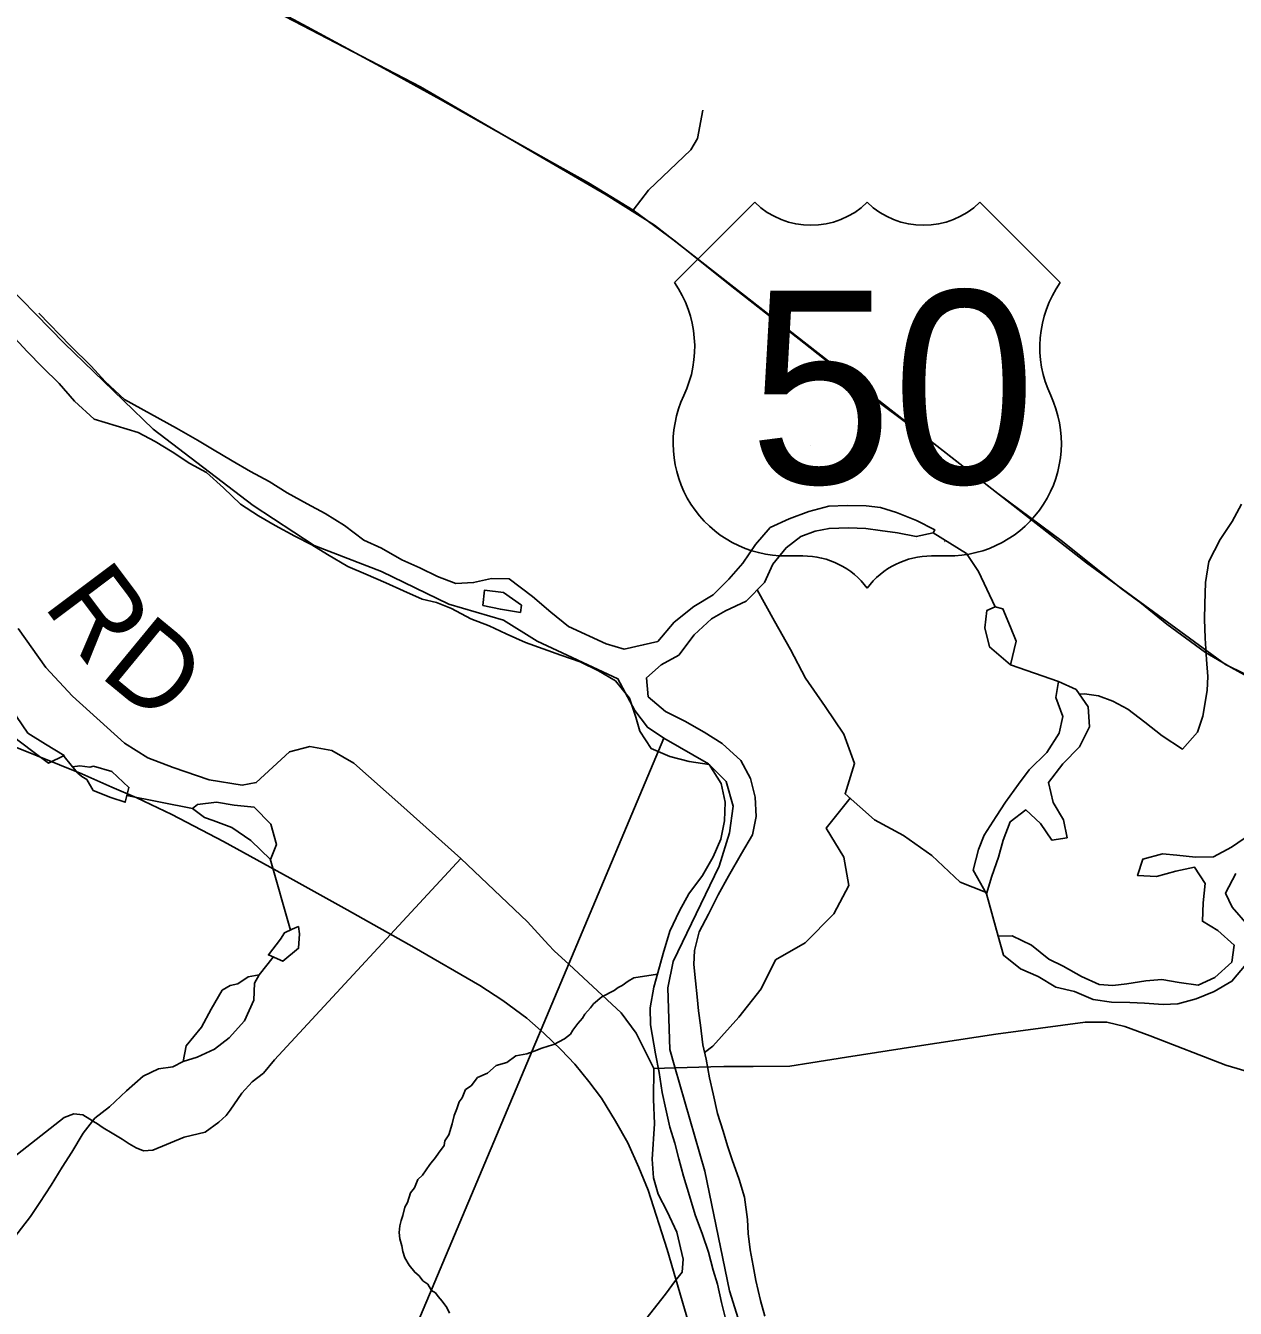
# Model space of a CAD drawing. Extents: x 0 to 34, y 0 to 22.
# Drawn here: x 3.416 to 4.243, y 19.852 to 20.729 of the extents above; entities that cross this region are included whole.
import ezdxf

# ---------------------------------------------------------------- set-up
doc = ezdxf.new("R2010")
doc.units = 0
for name, color, linetype in [('GM_X_Corporation', 7, 'Continuous'), ('GM_X_County_Road', 7, 'Continuous'), ('GM_X_Major_River', 7, 'Continuous'), ('GM_X_Minor_Lake', 7, 'Continuous'), ('GM_X_Minor_River', 7, 'Continuous'), ('GM_X_Rail_Line', 7, 'Continuous'), ('GM_X_Township_Road', 7, 'Continuous'), ('GM_X_Township_Road_Text', 7, 'Continuous'), ('GM_X_US_Location', 7, 'Continuous'), ('GM_X_US_Route', 7, 'Continuous'), ('GM_X_US_Shield', 7, 'Continuous')]:
    doc.layers.add(name, color=color, linetype=linetype)

msp = doc.modelspace()

# ---------------------------------------------------------------- linework, layer by layer
at = {"layer": 'GM_X_Corporation'}
for points in [[(2.97186, 18.15329), (3.78717, 20.08795), (3.85216, 20.24216), (3.84089, 20.24968), (3.83227, 20.26117), (3.82078, 20.28273), (3.76546, 20.3086), (3.74247, 20.32296), (3.70512, 20.33374), (3.65915, 20.35602), (3.61316, 20.37398), (3.5715, 20.40129), (3.50317, 20.45336), (3.44218, 20.5121), (3.34506, 20.61151), (3.32473, 20.67025), (3.32248, 20.70188), (3.35184, 20.80129)], [(3.34506, 20.61151), (3.44218, 20.5121), (3.50317, 20.45336), (3.5715, 20.40129), (3.61316, 20.37398), (3.65915, 20.35602), (3.70512, 20.33374), (3.74247, 20.32296), (3.76546, 20.3086), (3.82078, 20.28273), (3.83227, 20.26117), (3.84089, 20.24968), (3.85216, 20.24216), (3.88265, 20.22457), (3.8947, 20.21252), (3.89951, 20.19566), (3.89711, 20.17758), (3.88987, 20.1547), (3.85856, 20.08964), (3.85494, 20.07157), (3.85615, 20.0294), (3.85963, 20.01736), (3.88023, 19.94628), (3.89709, 19.86435), (3.91876, 19.79448)], [(3.91876, 19.79448), (3.89709, 19.86435), (3.88023, 19.94628), (3.85963, 20.01736), (3.85615, 20.0294), (3.85494, 20.07157), (3.85856, 20.08964), (3.88987, 20.1547), (3.89711, 20.17758), (3.89951, 20.19566), (3.8947, 20.21252), (3.88265, 20.22457), (3.85216, 20.24216), (3.78717, 20.08795), (2.97186, 18.15329)]]:
    msp.add_lwpolyline(points, dxfattribs=at)
at = {"layer": 'GM_X_County_Road'}
for points in [[(3.95265, 20.02035), (3.97685, 20.02411), (4.02527, 20.03179), (4.07902, 20.0398), (4.14002, 20.04807), (4.15481, 20.04815), (4.16716, 20.04514), (4.18452, 20.0388), (4.23628, 20.01876), (4.25397, 20.01343), (4.26232, 20.01251), (4.26966, 20.01275), (4.28062, 20.01725), (4.29626, 20.0276), (4.39506, 20.1048), (4.47516, 20.16515), (4.49823, 20.17943)], [(3.80963, 19.80691), (3.85335, 19.86208), (3.86004, 19.8714), (3.86456, 19.87721), (3.8653, 19.88611), (3.8611, 19.90464), (3.85443, 19.91872), (3.84831, 19.9305), (3.84504, 19.94169), (3.84406, 19.95454), (3.84578, 19.9785), (3.84504, 19.99555), (3.8453, 20.01643)], [(3.8453, 20.01643), (3.85986, 20.01684), (3.88427, 20.01752)], [(3.88427, 20.01752), (3.89305, 20.01776), (3.91308, 20.01776), (3.93812, 20.0181), (3.95265, 20.02035)]]:
    msp.add_lwpolyline(points, dxfattribs=at)
at = {"layer": 'GM_X_Major_River'}
for p, q in [((3.75409, 20.3282), (3.75494, 20.33313)), ((4.08895, 20.29223), (4.09301, 20.30851))]:
    msp.add_line(p, q, dxfattribs=at)
for points in [[(3.42501, 20.5327), (3.44657, 20.5103), (3.46071, 20.49639), (3.47038, 20.48597), (3.48341, 20.47359), (3.51909, 20.45413)], [(3.40581, 20.51854), (3.41696, 20.50657), (3.42737, 20.49576), (3.43891, 20.48455), (3.44931, 20.47259), (3.46272, 20.46021), (3.49283, 20.45115)], [(3.49283, 20.45115), (3.5045, 20.44487), (3.51617, 20.43783), (3.5282, 20.43003), (3.53949, 20.42376), (3.5511, 20.4133), (3.56269, 20.40209), (3.5751, 20.39428), (3.58639, 20.38763), (3.59995, 20.38018), (3.61163, 20.37428), (3.62216, 20.36765), (3.63608, 20.35943), (3.64853, 20.35428), (3.66211, 20.34835), (3.67418, 20.34283), (3.687, 20.33729), (3.69684, 20.33485), (3.70703, 20.33088), (3.72022, 20.32382), (3.73267, 20.31905), (3.74436, 20.31353), (3.75756, 20.30761), (3.78173, 20.29885), (3.79496, 20.29445), (3.80739, 20.28816), (3.81906, 20.2815), (3.82874, 20.26955), (3.83309, 20.25656), (3.8356, 20.24701), (3.84338, 20.2351), (3.85621, 20.22956), (3.86945, 20.2263), (3.88309, 20.22417), (3.89124, 20.21111), (3.89407, 20.19852), (3.89348, 20.1856), (3.891, 20.1731), (3.88587, 20.16102), (3.87844, 20.14822), (3.86912, 20.13582), (3.86286, 20.12414), (3.85617, 20.11019), (3.85175, 20.09505), (3.84811, 20.08181), (3.8453, 20.07197), (3.84279, 20.05794), (3.84298, 20.04616), (3.84646, 20.02633), (3.84891, 20.01374), (3.85097, 20.00002), (3.85344, 19.98858), (3.85628, 19.97636), (3.85952, 19.96529), (3.86239, 19.95459), (3.86562, 19.94275), (3.86958, 19.92938), (3.87355, 19.91639), (3.87865, 19.903), (3.88263, 19.89077), (3.88585, 19.87855), (3.88873, 19.869), (3.89157, 19.85641), (3.89442, 19.84457)], [(3.51909, 20.45413), (3.53339, 20.44591), (3.54355, 20.43966), (3.55709, 20.43183), (3.56951, 20.4244), (3.58232, 20.41773), (3.59473, 20.40992), (3.60828, 20.40247), (3.62071, 20.3958), (3.63387, 20.3876), (3.64701, 20.3775), (3.65908, 20.37197), (3.673, 20.36414), (3.68545, 20.35861), (3.69751, 20.35271), (3.70997, 20.34794), (3.72213, 20.3485), (3.73434, 20.35134), (3.74649, 20.35113), (3.76225, 20.33909), (3.77499, 20.32823), (3.78699, 20.31853), (3.81263, 20.3067), (3.82511, 20.30307), (3.83807, 20.3059), (3.84799, 20.30839), (3.85922, 20.32151), (3.87269, 20.33231), (3.88573, 20.34008), (3.89654, 20.35093), (3.90622, 20.36179), (3.91478, 20.37457), (3.92484, 20.38619), (3.93786, 20.39206), (3.95123, 20.39716), (3.96497, 20.40073), (3.97751, 20.40129), (3.99043, 20.40107), (4.00028, 20.39977), (4.01125, 20.39654), (4.02483, 20.391), (4.03727, 20.38471), (4.03623, 20.38261)], [(4.03623, 20.38261), (4.02465, 20.37998), (4.01178, 20.38247), (4.00003, 20.38418), (3.99017, 20.38549), (3.97841, 20.38606), (3.9651, 20.38552), (3.95558, 20.38378), (3.94564, 20.38015), (3.93564, 20.37233), (3.92672, 20.36107), (3.92082, 20.34862), (3.90845, 20.3359), (3.89429, 20.32929), (3.88471, 20.32375), (3.87275, 20.31292), (3.86227, 20.29903), (3.85039, 20.29239), (3.84037, 20.28343), (3.8413, 20.27049), (3.85329, 20.2604), (3.86648, 20.25372), (3.87965, 20.24628), (3.89206, 20.23847), (3.90479, 20.22685), (3.91143, 20.21458), (3.91464, 20.20198), (3.91519, 20.18867), (3.9127, 20.17616), (3.90528, 20.16336), (3.89629, 20.14792), (3.88925, 20.13511), (3.88257, 20.12192), (3.8763, 20.10985), (3.87305, 20.09698), (3.87252, 20.08749), (3.87386, 20.07644), (3.87482, 20.0654), (3.87581, 20.05588), (3.87716, 20.04597), (3.87885, 20.03264), (3.88097, 20.02272), (3.88342, 20.01013), (3.8859, 19.99907), (3.88873, 19.98571), (3.89271, 19.97348), (3.89558, 19.96355), (3.89885, 19.95399), (3.90357, 19.94061), (3.90717, 19.92838), (3.9092, 19.91314), (3.90981, 19.90362), (3.91115, 19.89258), (3.91325, 19.88152), (3.91499, 19.87161), (3.91818, 19.85787), (3.92105, 19.84717)], [(4.03623, 20.38261), (4.05904, 20.36838), (4.06719, 20.35608), (4.07855, 20.33198)], [(3.75494, 20.33313), (3.74254, 20.3417), (3.72965, 20.34343), (3.72834, 20.33281)], [(3.72834, 20.33281), (3.74046, 20.33032), (3.75409, 20.3282)], [(4.07855, 20.33198), (4.07284, 20.32937), (4.07151, 20.31761), (4.07472, 20.30463), (4.08895, 20.29223)], [(4.09301, 20.30851), (4.08899, 20.31808), (4.08388, 20.33071), (4.07855, 20.33198)], [(4.08895, 20.29223), (4.12182, 20.28104)], [(4.12182, 20.28104), (4.12012, 20.27004), (4.12485, 20.25704), (4.12239, 20.24567), (4.11382, 20.23251), (4.10184, 20.22054), (4.09447, 20.21078), (4.08553, 20.19838), (4.0793, 20.1886), (4.07111, 20.17581), (4.06715, 20.166), (4.06351, 20.15199), (4.07274, 20.13587)], [(4.07274, 20.13587), (4.07636, 20.14797), (4.08074, 20.16083), (4.08397, 20.17256), (4.08873, 20.18503), (4.09951, 20.19321), (4.10961, 20.18392), (4.1174, 20.17238), (4.12769, 20.17411), (4.12522, 20.18632), (4.1182, 20.19822), (4.115, 20.21196), (4.12471, 20.22472), (4.13629, 20.23632), (4.14297, 20.2499), (4.14205, 20.2636), (4.13389, 20.27552), (4.12182, 20.28104)], [(4.25385, 20.17696), (4.24003, 20.16769), (4.22776, 20.16105), (4.2156, 20.16087), (4.20271, 20.16222), (4.19285, 20.16315), (4.17949, 20.15957), (4.17589, 20.14822), (4.1888, 20.14763), (4.20215, 20.15121), (4.21473, 20.15404), (4.22215, 20.14289), (4.2208, 20.12961), (4.22021, 20.11707), (4.23075, 20.11082), (4.24198, 20.10075), (4.24027, 20.08899), (4.22871, 20.07854), (4.21723, 20.0734), (4.20434, 20.07514), (4.19259, 20.07723), (4.18156, 20.07628), (4.16861, 20.07421), (4.1591, 20.07323), (4.14961, 20.07377), (4.13755, 20.07929), (4.12512, 20.08634), (4.11532, 20.09106), (4.10332, 20.10076), (4.09013, 20.10707), (4.08063, 20.10685)], [(4.25132, 20.11428), (4.2405, 20.12662), (4.2361, 20.1362), (4.24316, 20.14977)], [(4.07274, 20.13587), (4.08063, 20.10685)], [(4.08063, 20.10685), (4.08422, 20.09386), (4.09584, 20.08454), (4.10792, 20.0794), (4.11995, 20.07197), (4.13282, 20.0691), (4.14565, 20.06357), (4.15816, 20.06184), (4.17069, 20.06163), (4.18056, 20.06108), (4.19346, 20.06011), (4.20334, 20.06071), (4.21593, 20.06392), (4.22817, 20.06904), (4.24044, 20.07606), (4.25013, 20.08768)]]:
    msp.add_lwpolyline(points, dxfattribs=at)
at = {"layer": 'GM_X_Minor_Lake'}
msp.add_lwpolyline([(4.1361, 20.27229), (4.13966, 20.27243), (4.14915, 20.27113), (4.15898, 20.26754), (4.16916, 20.26204), (4.18079, 20.25309), (4.1928, 20.24375), (4.20672, 20.23477), (4.21682, 20.24637), (4.22043, 20.25734), (4.2234, 20.27477), (4.22395, 20.28426), (4.22301, 20.29607), (4.22212, 20.31053), (4.22159, 20.32346), (4.22177, 20.33372), (4.22241, 20.34854), (4.22456, 20.36294), (4.23243, 20.37801), (4.24064, 20.39041), (4.24693, 20.40209)], dxfattribs=at)
at = {"layer": 'GM_X_Minor_River'}
for points in [[(4.02494, 20.37793), (4.02494, 20.37793)], [(4.04416, 20.37649), (4.04399, 20.37654)], [(3.91597, 20.34363), (3.92778, 20.32209), (3.93879, 20.30271), (3.94904, 20.28332), (3.96233, 20.26394), (3.97524, 20.24493), (3.98246, 20.22479), (3.976, 20.20426), (3.99612, 20.1864), (4.01587, 20.17575), (4.03524, 20.16207), (4.0546, 20.14382), (4.07208, 20.13703)], [(3.36902, 20.31921), (3.37649, 20.31544), (3.38926, 20.30647), (3.39971, 20.2945), (3.40367, 20.28189), (3.40649, 20.26892), (3.40971, 20.25707), (3.41749, 20.24554), (3.42954, 20.2381), (3.44234, 20.23027), (3.4316, 20.22514), (3.41995, 20.23371), (3.40756, 20.24305), (3.40054, 20.25496), (3.39695, 20.26756), (3.39678, 20.27935), (3.39282, 20.29197)], [(3.44145, 20.23082), (3.44791, 20.22257)], [(3.46208, 20.20636), (3.45765, 20.21404), (3.45426, 20.216), (3.45164, 20.21833), (3.44791, 20.22257), (3.45287, 20.22325), (3.4597, 20.22237), (3.46237, 20.22308)], [(3.46237, 20.22308), (3.47487, 20.21944), (3.48647, 20.20859), (3.48401, 20.19837), (3.47418, 20.20159), (3.46208, 20.20636)], [(3.48511, 20.20294), (3.52997, 20.19415)], [(3.97951, 20.20114), (3.96309, 20.18069), (3.97524, 20.16093), (3.97866, 20.14154), (3.9684, 20.12215), (3.94865, 20.10239), (3.92853, 20.09061), (3.91865, 20.07084), (3.90346, 20.05145), (3.88562, 20.03169), (3.88, 20.02727)], [(3.53344, 20.19675), (3.52997, 20.19415), (3.53823, 20.18792), (3.54406, 20.18599)], [(3.53344, 20.19675), (3.5464, 20.19842), (3.55854, 20.19631), (3.57221, 20.19493), (3.58342, 20.18333), (3.58737, 20.16957), (3.58339, 20.15938), (3.56991, 20.17216), (3.55675, 20.18114), (3.54406, 20.18599)], [(3.58308, 20.15967), (3.5969, 20.111)], [(3.60304, 20.10848), (3.60237, 20.11343), (3.59815, 20.11161), (3.59278, 20.10904), (3.59005, 20.1049)], [(3.60304, 20.10848), (3.60249, 20.0986), (3.59168, 20.08967), (3.58186, 20.09402), (3.59005, 20.1049)], [(3.58507, 20.0926), (3.57554, 20.08045)], [(3.5724, 20.0748), (3.57554, 20.08045), (3.56791, 20.07906), (3.56098, 20.07424), (3.55563, 20.07319), (3.55025, 20.06987)], [(3.84784, 20.08085), (3.83161, 20.07835), (3.82777, 20.07613), (3.82354, 20.07317), (3.82085, 20.07169), (3.81816, 20.06984), (3.80972, 20.06542), (3.80394, 20.06058), (3.80199, 20.05795), (3.79811, 20.05345), (3.79655, 20.05082), (3.79344, 20.04707), (3.78994, 20.04256), (3.78838, 20.03993), (3.78414, 20.03658), (3.77686, 20.0329), (3.7738, 20.03182), (3.76806, 20.03001), (3.76538, 20.02892), (3.7585, 20.02638), (3.75087, 20.02499), (3.74471, 20.02053), (3.73745, 20.01838), (3.73166, 20.01315), (3.72477, 20.01023), (3.72049, 20.0046), (3.71665, 20.002), (3.71427, 19.99634), (3.71232, 19.99372), (3.71072, 19.9888), (3.70874, 19.98427), (3.70751, 19.97858), (3.7051, 19.97102), (3.70237, 19.96688), (3.70194, 19.96385), (3.69804, 19.95859), (3.69609, 19.95558), (3.69221, 19.9507), (3.68715, 19.94357), (3.68405, 19.94058), (3.68168, 19.93491), (3.67896, 19.93154), (3.67694, 19.92473), (3.67499, 19.92172), (3.67375, 19.91603), (3.67256, 19.91263), (3.67173, 19.90884), (3.67128, 19.90429), (3.67158, 19.9001), (3.67302, 19.89513), (3.67372, 19.89131), (3.67517, 19.8871), (3.67812, 19.8821), (3.68184, 19.87709), (3.68484, 19.87476), (3.68745, 19.87129), (3.69083, 19.86895), (3.69342, 19.86472), (3.69605, 19.86315), (3.69791, 19.86046), (3.70052, 19.85737), (3.70387, 19.85312), (3.7057, 19.84929)], [(3.5724, 20.0748), (3.57181, 20.06303), (3.56548, 20.04907), (3.55501, 20.03747), (3.54498, 20.02966), (3.53309, 20.02417), (3.52353, 20.02129), (3.52562, 20.0319), (3.53611, 20.04464), (3.5428, 20.05707), (3.55025, 20.06987)], [(3.52353, 20.02129), (3.51662, 20.01761), (3.5067, 20.01627), (3.49634, 20.01113), (3.48475, 20.00107), (3.47315, 19.99024), (3.46312, 19.98244), (3.45533, 19.97231), (3.4475, 19.95914), (3.44085, 19.94899), (3.43341, 19.93658), (3.42559, 19.92493), (3.41934, 19.91516), (3.40689, 19.89941), (3.40025, 19.88964), (3.39398, 19.87911), (3.38154, 19.86412), (3.36988, 19.84988), (3.35781, 19.83412), (3.34504, 19.82142), (3.33235, 19.81404), (3.3189, 19.80629), (3.30698, 19.7989)]]:
    msp.add_lwpolyline(points, dxfattribs=at)
at = {"layer": 'GM_X_Rail_Line'}
for points in [[(4.28982, 20.26607), (4.23593, 20.29254), (4.14098, 20.36198), (3.84563, 20.59275), (3.81259, 20.61361), (3.68577, 20.68742), (3.58196, 20.74139), (3.38565, 20.85256), (3.35268, 20.86953), (3.24301, 20.9)], [(3.28626, 20.28552), (3.45435, 20.21777), (3.47491, 20.20882), (3.49183, 20.20141), (3.51575, 20.19008), (3.55127, 20.17162), (3.59666, 20.14645), (3.6356, 20.12477), (3.68148, 20.09903), (3.72637, 20.07316), (3.74217, 20.06295), (3.7584, 20.05092), (3.77014, 20.04057), (3.78203, 20.02911), (3.79126, 20.01932), (3.80091, 20.00757), (3.80944, 19.9961), (3.81909, 19.98044), (3.82749, 19.96561), (3.83504, 19.94883), (3.84147, 19.9333), (3.85448, 19.89275), (3.8721, 19.83191)]]:
    msp.add_lwpolyline(points, dxfattribs=at)
at = {"layer": 'GM_X_Township_Road'}
for points in [[(3.83122, 20.60301), (3.84164, 20.61686), (3.8705, 20.6444), (3.87515, 20.65199), (3.87878, 20.6715)], [(3.41093, 20.31725), (3.42963, 20.29054), (3.44799, 20.27085), (3.48338, 20.23879), (3.49941, 20.22877), (3.51677, 20.2221), (3.54147, 20.21375), (3.56384, 20.21008), (3.57352, 20.2118), (3.59623, 20.23278), (3.61025, 20.23645), (3.62528, 20.23378), (3.6403, 20.2251), (3.67236, 20.19672), (3.71342, 20.15999), (3.75883, 20.11659), (3.7734, 20.10097)], [(3.4635, 19.97952), (3.46442, 19.97896), (3.46881, 19.97596), (3.47505, 19.97226), (3.48198, 19.96811), (3.4866, 19.96487), (3.49145, 19.9621), (3.49654, 19.96025), (3.50277, 19.96048), (3.52426, 19.96949), (3.53873, 19.97281), (3.54802, 19.97978), (3.55306, 19.9842), (3.55581, 19.98792), (3.5637, 19.99949), (3.57073, 20.00727), (3.57846, 20.01315), (3.58591, 20.02244), (3.71342, 20.15999)], [(3.7734, 20.10097), (3.7772, 20.09689), (3.7874, 20.08743), (3.82293, 20.05449), (3.83329, 20.04047), (3.8453, 20.01643)], [(3.11896, 19.90119), (3.12409, 19.89787), (3.13079, 19.89047), (3.13541, 19.88192), (3.13818, 19.87361), (3.14165, 19.86737), (3.14927, 19.86182), (3.15828, 19.85859), (3.16799, 19.8579), (3.18381, 19.85956), (3.20449, 19.86506), (3.22783, 19.87083), (3.25255, 19.87592), (3.28405, 19.88609), (3.3251, 19.90503), (3.35882, 19.91906), (3.37196, 19.92858), (3.39091, 19.94289), (3.44237, 19.98292), (3.44894, 19.98543), (3.45495, 19.98474), (3.4598, 19.98174), (3.4635, 19.97952)]]:
    msp.add_lwpolyline(points, dxfattribs=at)
at = {"layer": 'GM_X_US_Route'}
for points in [[(3.24098, 20.9), (3.24849, 20.89793), (3.28831, 20.88825), (3.32672, 20.8773), (3.35488, 20.86834), (3.3728, 20.86066), (3.39158, 20.85127), (3.42458, 20.83136), (3.46242, 20.81088), (3.51592, 20.7801), (3.56369, 20.75256), (3.60834, 20.72838), (3.66097, 20.69993), (3.69939, 20.67865), (3.74831, 20.65129), (3.77533, 20.63593), (3.80065, 20.6217), (3.83122, 20.60301), (3.85996, 20.58193), (3.89737, 20.55177), (3.94773, 20.5125), (3.96744, 20.49689), (3.97303, 20.49296)], [(3.97303, 20.49296), (3.98581, 20.48397), (4.00009, 20.47105), (4.03161, 20.44746), (4.08036, 20.40937), (4.12465, 20.37669), (4.16472, 20.34452), (4.17674, 20.33567), (4.17751, 20.33505)], [(4.17751, 20.33505), (4.19601, 20.32003), (4.22231, 20.30075), (4.23977, 20.29054), (4.25814, 20.28057), (4.27174, 20.27286), (4.2883, 20.26674), (4.30635, 20.26076)]]:
    msp.add_lwpolyline(points, dxfattribs=at)
at = {"layer": 'GM_X_US_Shield'}
for p, q in [((3.91423, 20.60848), (3.8593, 20.55355)), ((4.12297, 20.55355), (4.06804, 20.60848)), ((3.93621, 20.36678), (3.94719, 20.36678)), ((4.03508, 20.36678), (4.04607, 20.36678))]:
    msp.add_line(p, q, dxfattribs=at)
for centre, radius, start, end in [((3.95269, 20.64771), 0.05493, 225.573, 314.427), ((4.02959, 20.64771), 0.05493, 225.573, 314.427), ((3.79631, 20.50944), 0.0769, 334.54712, 35.00093), ((4.18597, 20.50944), 0.0769, 144.99907, 205.45288), ((3.93535, 20.44368), 0.0769, 154.83192, 270.63826), ((4.04693, 20.44368), 0.0769, 269.36174, 25.16808), ((3.94719, 20.31185), 0.05493, 36.8699, 90), ((4.03508, 20.31185), 0.05493, 90, 143.1301)]:
    msp.add_arc(centre, radius, start, end, dxfattribs=at)

# ---------------------------------------------------------------- texts
at = {"layer": 'GM_X_Township_Road_Text'}
for s, rotation, p in [('R', 306.89488, (3.42732, 20.33307)), ('D', 320.53698, (3.46534, 20.28527))]:
    msp.add_text(s, height=0.05682, rotation=rotation, dxfattribs=at).set_placement(p)
at = {"layer": 'GM_X_US_Location'}
for s, p in [('0', (3.99107, 20.4811)), ('/', (3.99109, 20.4811))]:
    msp.add_text(s, height=0.000189, dxfattribs=at).set_placement(p)
msp.add_text('50', height=0.000189, rotation=0.00001, dxfattribs=at).set_placement((3.95197, 20.44189))
at = {"layer": 'GM_X_US_Shield'}
msp.add_text('50', height=0.131836, dxfattribs=at).set_placement((3.91024, 20.41622))

doc.saveas('drawing.dxf')
